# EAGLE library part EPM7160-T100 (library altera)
EPM7160S MAX 7000 family
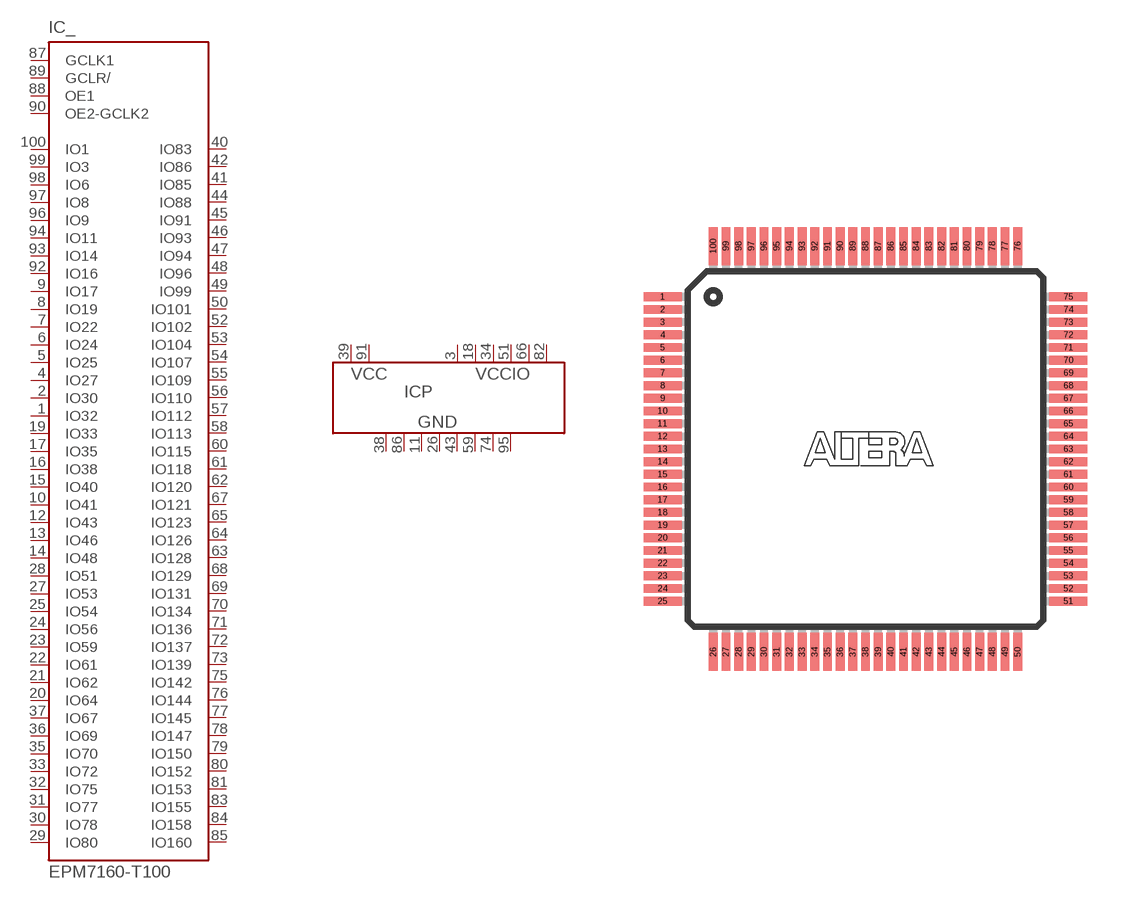
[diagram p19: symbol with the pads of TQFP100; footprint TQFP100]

Designator prefix IC; gates _=7160P100 P=PWR8-2-6

## EPM7160-T100  [TQFP100]
1  _:IO32
2  _:IO30
3  P:VCCIO  pwr
4  _:IO27
5  _:IO25
6  _:IO24
7  _:IO22
8  _:IO19
9  _:IO17
10  _:IO41
11  P:GND  pwr
12  _:IO43
13  _:IO46
14  _:IO48
15  _:IO40
16  _:IO38
17  _:IO35
18  P:VCCIO  pwr
19  _:IO33
20  _:IO64
21  _:IO62
22  _:IO61
23  _:IO59
24  _:IO56
25  _:IO54
26  P:GND  pwr
27  _:IO53
28  _:IO51
29  _:IO80
30  _:IO78
31  _:IO77
32  _:IO75
33  _:IO72
34  P:VCCIO  pwr
35  _:IO70
36  _:IO69
37  _:IO67
38  P:GND  pwr
39  P:VCC  pwr
40  _:IO83
41  _:IO85
42  _:IO86
43  P:GND  pwr
44  _:IO88
45  _:IO91
46  _:IO93
47  _:IO94
48  _:IO96
49  _:IO99
50  _:IO101
51  P:VCCIO  pwr
52  _:IO102
53  _:IO104
54  _:IO107
55  _:IO109
56  _:IO110
57  _:IO112
58  _:IO113
59  P:GND  pwr
60  _:IO115
61  _:IO118
62  _:IO120
63  _:IO128
64  _:IO126
65  _:IO123
66  P:VCCIO  pwr
67  _:IO121
68  _:IO129
69  _:IO131
70  _:IO134
71  _:IO136
72  _:IO137
73  _:IO139
74  P:GND  pwr
75  _:IO142
76  _:IO144
77  _:IO145
78  _:IO147
79  _:IO150
80  _:IO152
81  _:IO153
82  P:VCCIO  pwr
83  _:IO155
84  _:IO158
85  _:IO160
86  P:GND  pwr
87  _:GCLK1  in
88  _:OE1  in
89  _:GCLR/  in
90  _:OE2-GCLK2  in
91  P:VCC  pwr
92  _:IO16
93  _:IO14
94  _:IO11
95  P:GND  pwr
96  _:IO9
97  _:IO8
98  _:IO6
99  _:IO3
100  _:IO1

## Footprint TQFP100 (pad centres in mm)
Plastic Thin Quad Flat Pack
smd 1.5 x 0.35: 1 -8,6; 2 -8,5.5; 3 -8,5; 4 -8,4.5; 5 -8,4; 6 -8,3.5; 7 -8,3; 8 -8,2.5; 9 -8,2; 10 -8,1.5; 11 -8,1; 12 -8,0.5; 13 -8,0; 14 -8,-0.5; 15 -8,-1; 16 -8,-1.5; 17 -8,-2; 18 -8,-2.5; 19 -8,-3; 20 -8,-3.5; 21 -8,-4; 22 -8,-4.5; 23 -8,-5; 24 -8,-5.5; 25 -8,-6; 51 8,-6; 52 8,-5.5; 53 8,-5; 54 8,-4.5; 55 8,-4; 56 8,-3.5; 57 8,-3; 58 8,-2.5; 59 8,-2; 60 8,-1.5; 61 8,-1; 62 8,-0.5; 63 8,0; 64 8,0.5; 65 8,1; 66 8,1.5; 67 8,2; 68 8,2.5; 69 8,3; 70 8,3.5; 71 8,4; 72 8,4.5; 73 8,5; 74 8,5.5; 75 8,6
smd 0.35 x 1.5: 26 -6,-8; 27 -5.5,-8; 28 -5,-8; 29 -4.5,-8; 30 -4,-8; 31 -3.5,-8; 32 -3,-8; 33 -2.5,-8; 34 -2,-8; 35 -1.5,-8; 36 -1,-8; 37 -0.5,-8; 38 0,-8; 39 0.5,-8; 40 1,-8; 41 1.5,-8; 42 2,-8; 43 2.5,-8; 44 3,-8; 45 3.5,-8; 46 4,-8; 47 4.5,-8; 48 5,-8; 49 5.5,-8; 50 6,-8; 76 6,8; 77 5.5,8; 78 5,8; 79 4.5,8; 80 4,8; 81 3.5,8; 82 3,8; 83 2.5,8; 84 2,8; 85 1.5,8; 86 1,8; 87 0.5,8; 88 0,8; 89 -0.5,8; 90 -1,8; 91 -1.5,8; 92 -2,8; 93 -2.5,8; 94 -3,8; 95 -3.5,8; 96 -4,8; 97 -4.5,8; 98 -5,8; 99 -5.5,8; 100 -6,8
